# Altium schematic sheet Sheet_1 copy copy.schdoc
size 589 x 414 mm; Device: A_A2; Symbol: A_A2; Name: A_A2; Designator: A; @Project Name: Sheet_1; REV: 1.0; Date: 2023-12-10; Sheet: 1/1; Draw By: sheep_finder; Company: Your Company; Manufacturer Part: ?; Convert to PCB: yes; Add into BOM: yes; Origin Footprint: NONE; Unique ID: frame_lib_1
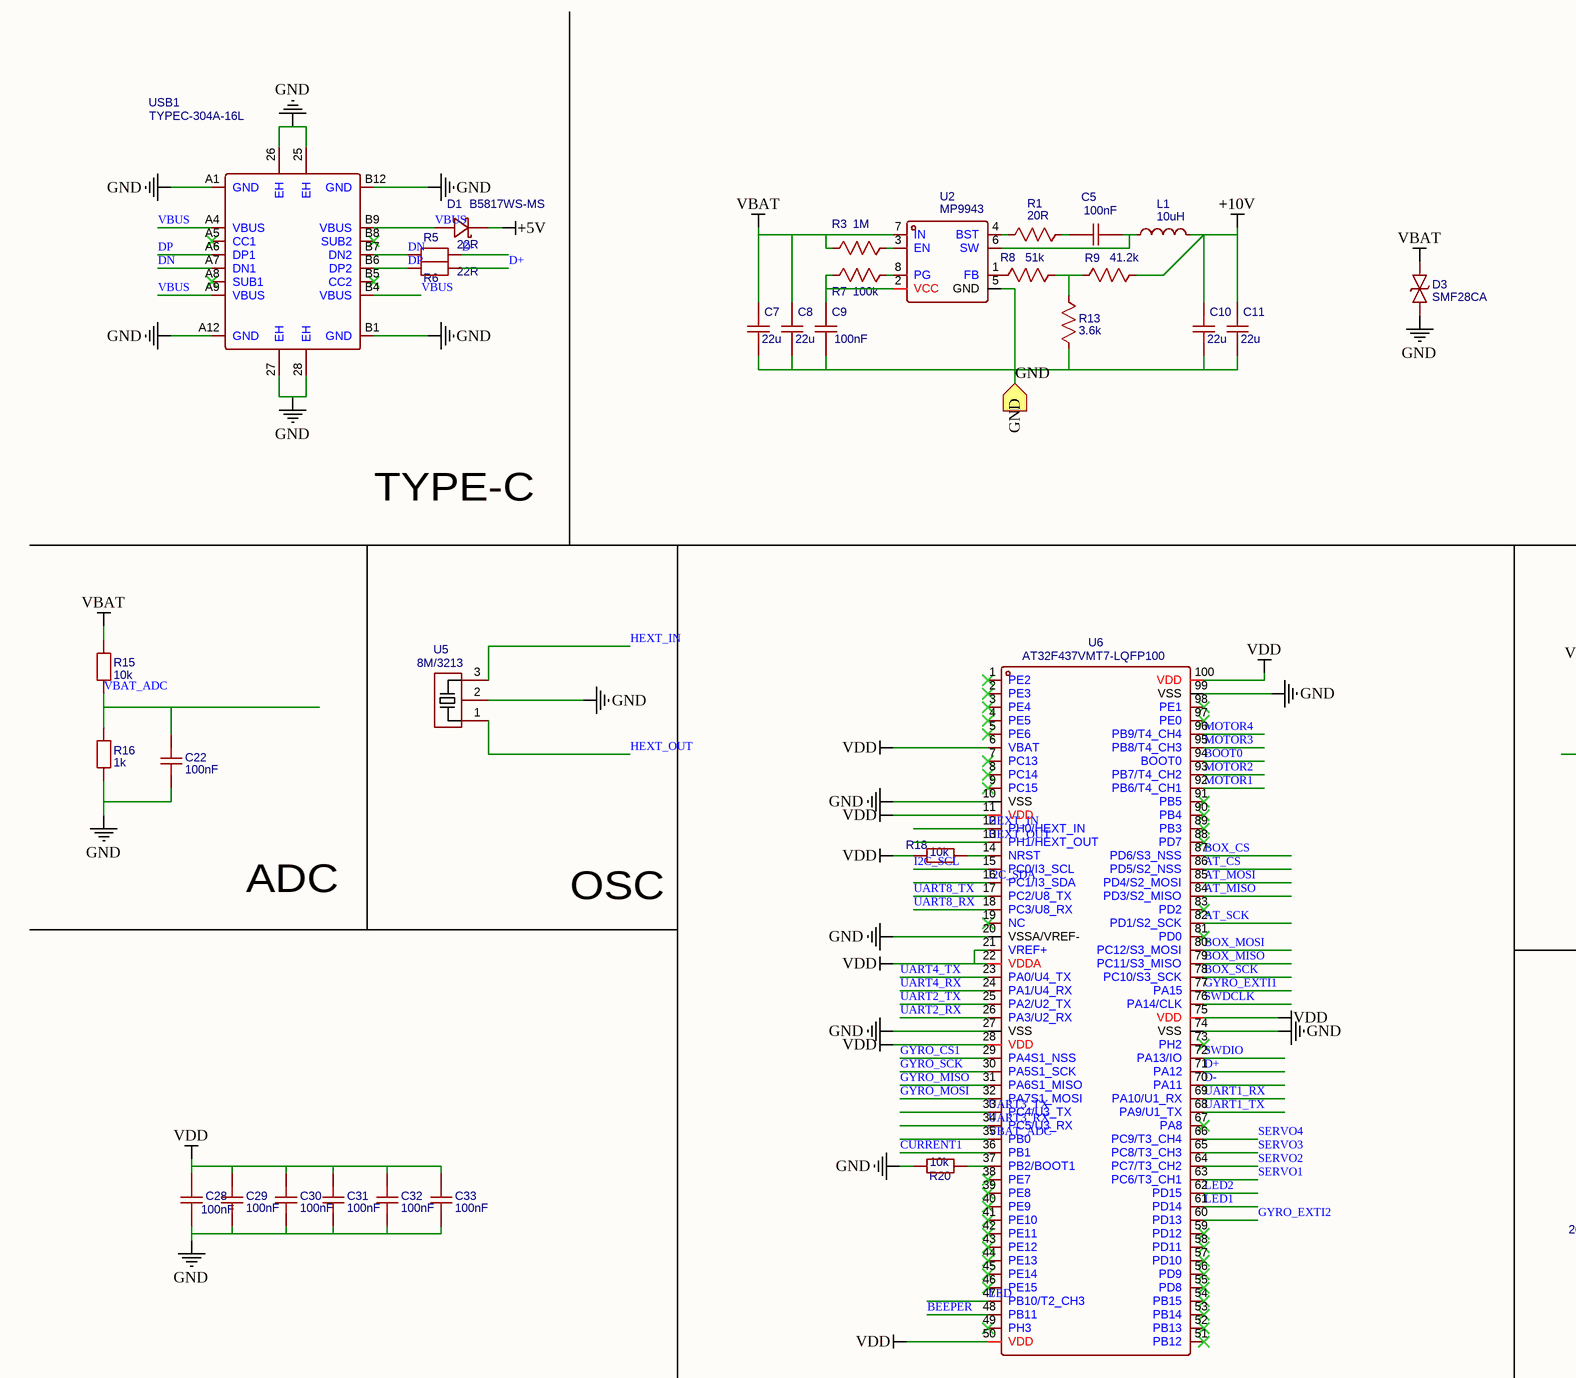
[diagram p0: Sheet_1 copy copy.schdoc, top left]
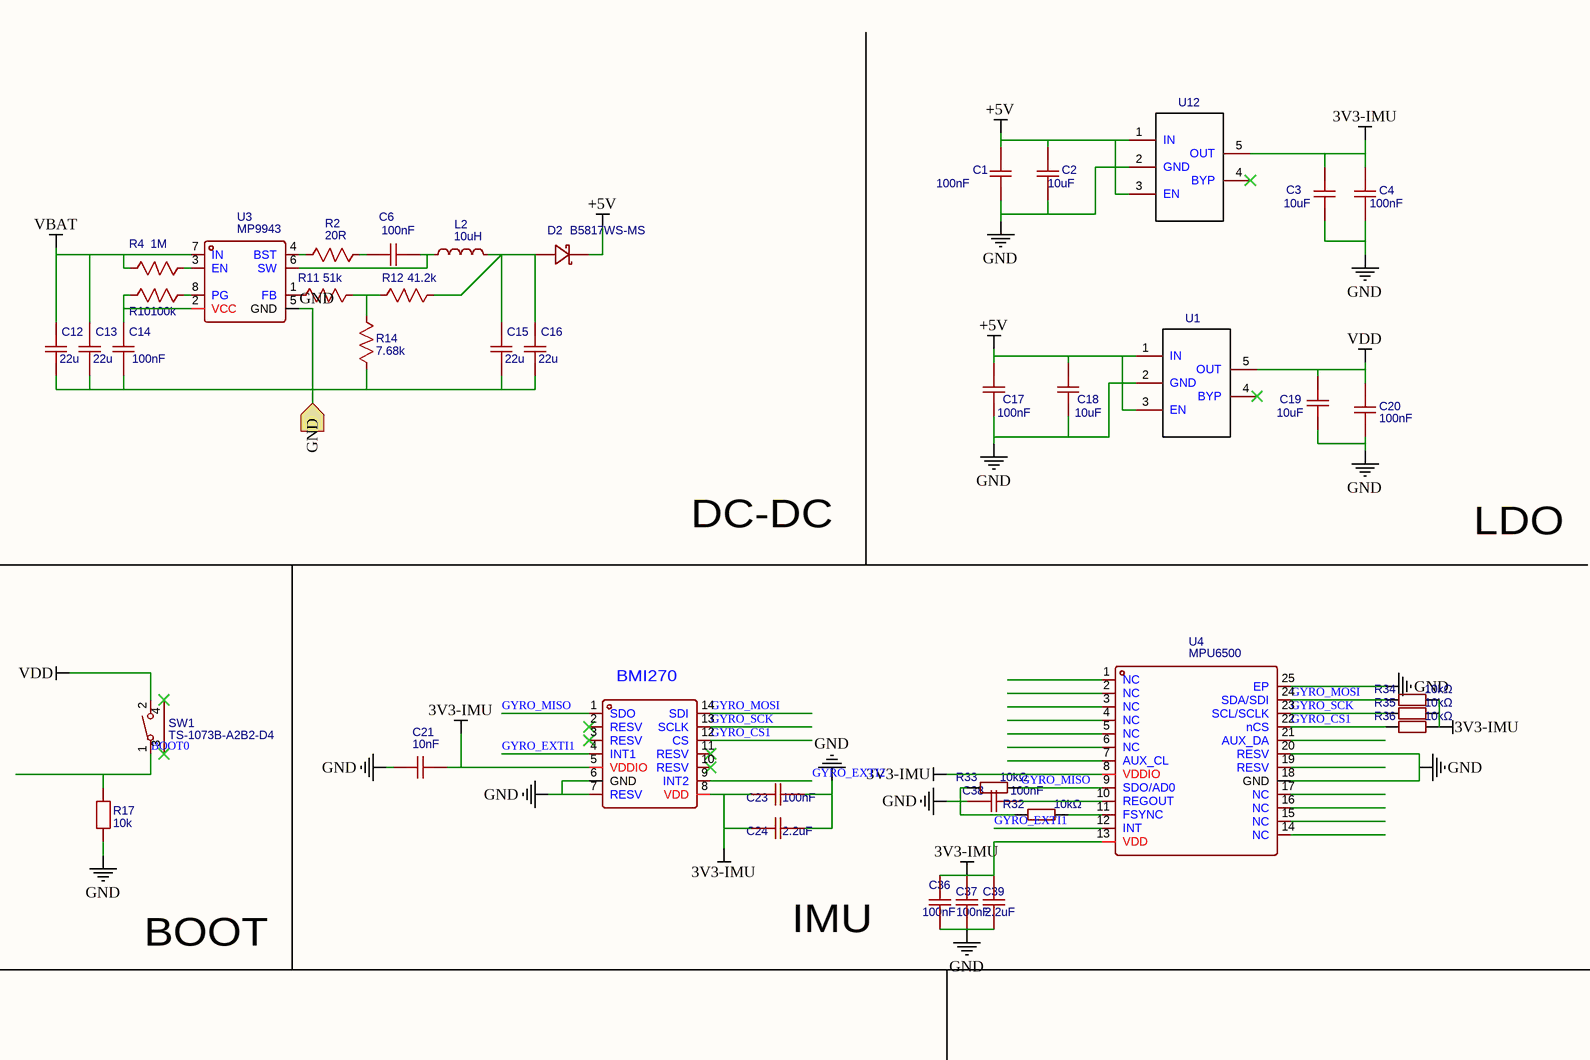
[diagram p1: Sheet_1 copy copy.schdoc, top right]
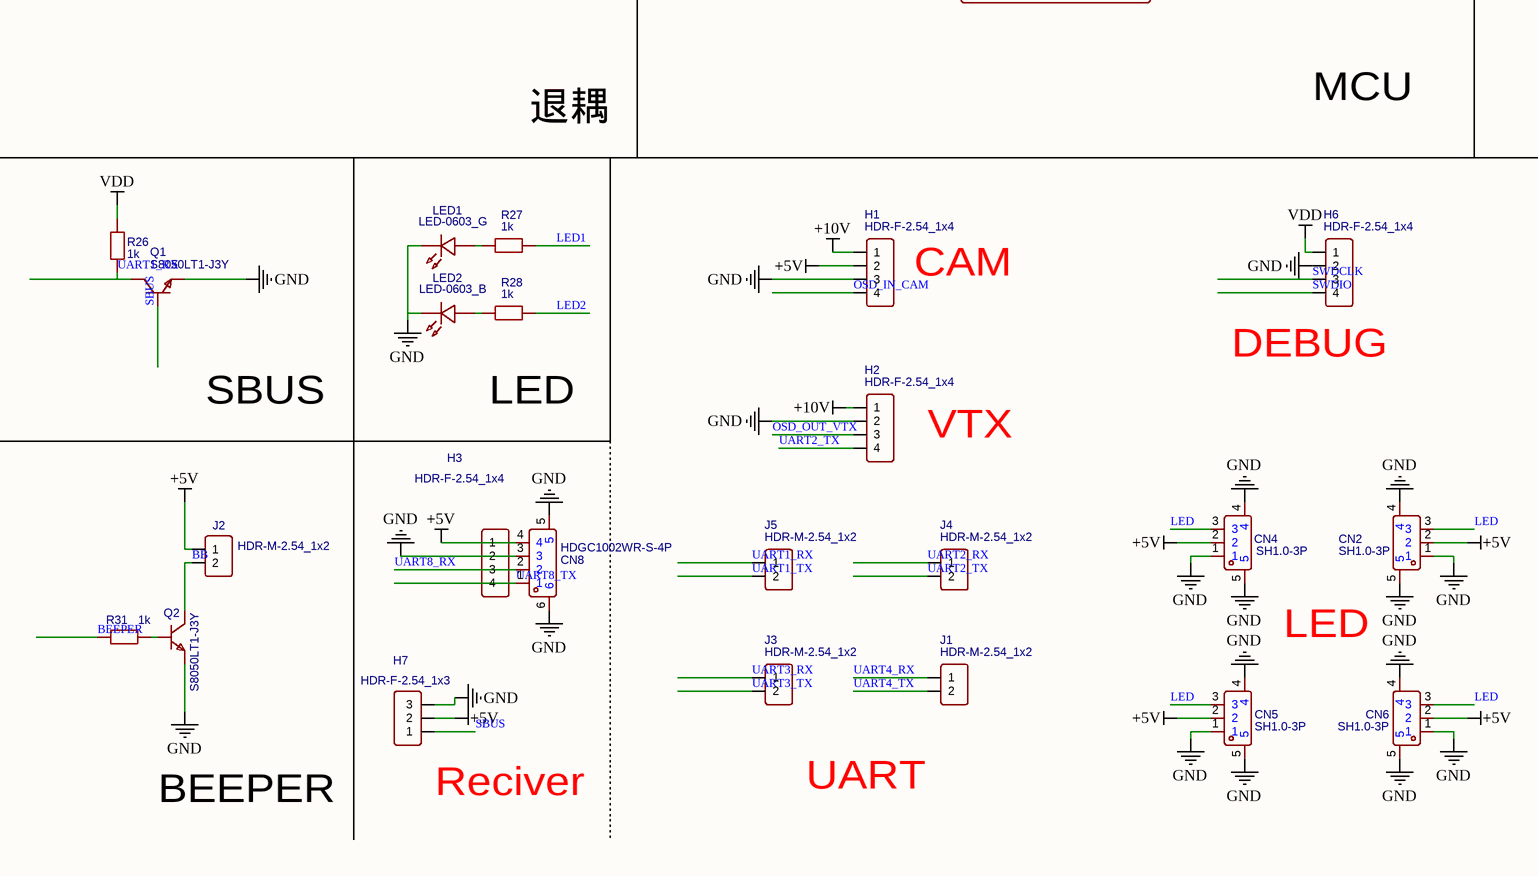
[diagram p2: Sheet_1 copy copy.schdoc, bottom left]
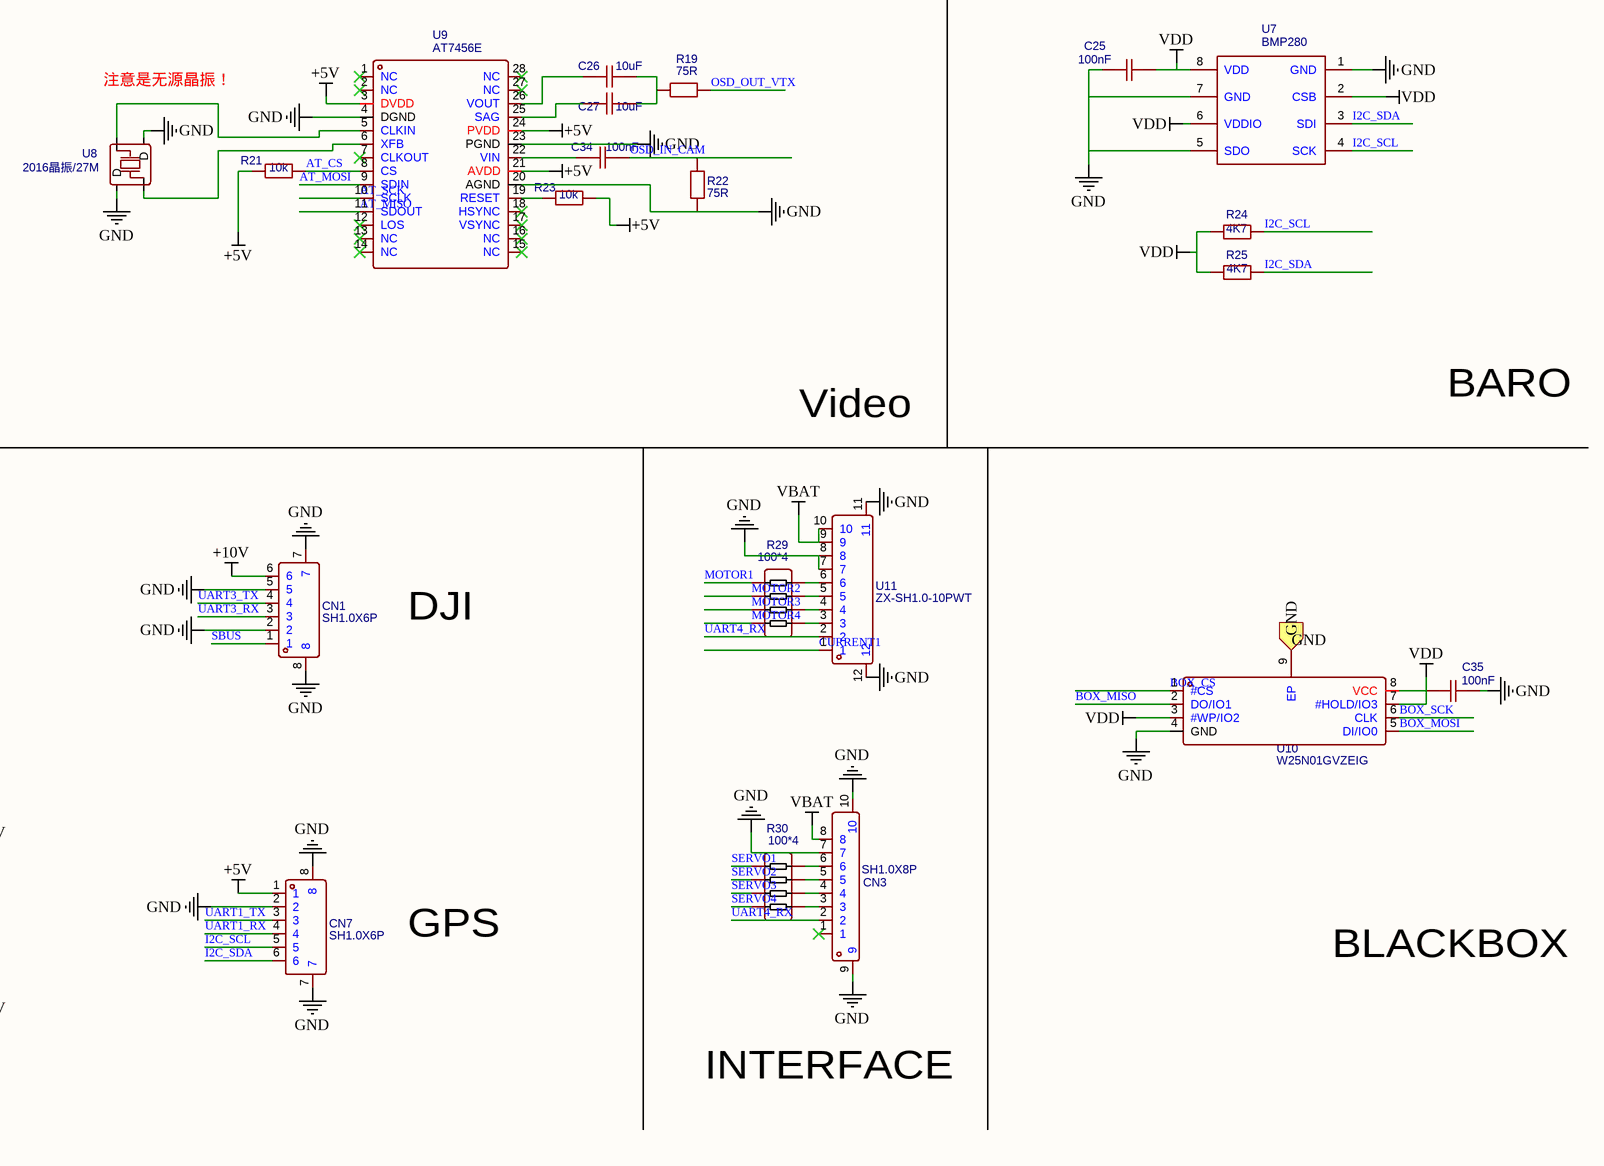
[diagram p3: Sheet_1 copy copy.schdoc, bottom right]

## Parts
C1  100nF  [C0603]
C2  10uF  [C0603]
C3  10uF  [C0603]
C4  100nF  [C0603]
C5  100nF  [C0603]
C6  100nF  [C0603]
C7  22u  [C0805]
C8  22u  [C0805]
C9  100nF  [C0603]
C10  22u  [C0805]
C11  22u  [C0805]
C12  22u  [C0805]
C13  22u  [C0805]
C14  100nF  [C0603]
C15  22u  [C0805]
C16  22u  [C0805]
C17  100nF  [C0603]
C18  10uF  [C0603]
C19  10uF  [C0603]
C20  100nF  [C0603]
C21  10nF  [C0603]
C22  100nF  [C0603]
C23  100nF  [C0603]
C24  2.2uF  [C0603]
C25  100nF  [C0603]
C26  10uF  [C0603]
C27  10uF  [C0603]
C28  100nF  [C0603]
C29  100nF  [C0603]
C30  100nF  [C0603]
C31  100nF  [C0603]
C32  100nF  [C0603]
C33  100nF  [C0603]
C34  100nF  [C0603]
C35  100nF  [C0603]
C36  100nF  [C0603]
C37  100nF  [C0603]
C38  100nF  [C0603]
C39  2.2uF  [C0603]
CN1  SH1.0X6P  [CONN-SMD_6P-P1.00_MEGASTAR_ZX-SH1.0-6PWT]
CN2  SH1.0-3P  [CONN-SMD_3P-P1.00_HDGC_HDGC1002WR-S-3P]
CN3  SH1.0X8P  [CONN-SMD_8P-P1.00_WAFER-SH1.0-8PWB]
CN4  SH1.0-3P  [CONN-SMD_3P-P1.00_HDGC_HDGC1002WR-S-3P]
CN5  SH1.0-3P  [CONN-SMD_3P-P1.00_HDGC_HDGC1002WR-S-3P]
CN6  SH1.0-3P  [CONN-SMD_3P-P1.00_HDGC_HDGC1002WR-S-3P]
CN7  SH1.0X6P  [CONN-SMD_6P-P1.00_MEGASTAR_ZX-SH1.0-6PWT]
CN8  HDGC1002WR-S-4P  [CONN-SMD_4P-P1.00_HDGC_HDGC1002WR-S-4P]
D1  B5817WS-MS  [SOD-323_L1.7-W1.3-LS2.7-FD]
D2  B5817WS-MS  [SOD-323_L1.7-W1.3-LS2.7-FD]
D3  SMF28CA  [SOD-123_L2.7-W1.8-LS3.7-BI]
H1  HDR-F-2.54_1x4
H2  HDR-F-2.54_1x4
H3  HDR-F-2.54_1x4
H6  HDR-F-2.54_1x4
H7  HDR-F-2.54_1x3
J1  HDR-M-2.54_1x2
J2  HDR-M-2.54_1x2
J3  HDR-M-2.54_1x2
J4  HDR-M-2.54_1x2
J5  HDR-M-2.54_1x2
L1  10uH  [IND-SMD_L4.4-W4.0_PHC0420]
L2  10uH  [IND-SMD_L4.4-W4.0_PHC0420]
LED1  LED-0603_G  [LED0603_GREEN]
LED2  LED-0603_B  [LED0603_BLUE]
Q1  S8050LT1-J3Y  [SOT-23_L2.9-W1.3-P1.90-LS2.4-BR]
Q2  S8050LT1-J3Y  [SOT-23_L2.9-W1.3-P1.90-LS2.4-BR]
R1  20R  [R0603]
R2  20R  [R0603]
R3  1M  [R0603]
R4  1M  [R0603]
R5  22R  [R0603]
R6  22R  [R0603]
R7  100k  [R0603]
R8  51k  [R0603]
R9  41.2k  [R0603]
R10  100k  [R0603]
R11  51k  [R0603]
R12  41.2k  [R0603]
R13  3.6k  [R0603]
R14  7.68k  [R0603]
R15  10k  [R0603]
R16  1k  [R0603]
R17  10k  [R0603]
R18  10k  [R0603]
R19  75R  [R0603]
R20  10k  [R0603]
R21  10k  [R0603]
R22  75R  [R0603]
R23  10k  [R0603]
R24  4K7  [R0603]
R25  4K7  [R0603]
R26  1k  [R0603]
R27  1k  [R0603]
R28  1k  [R0603]
R29  100*4  [RES-ARRAY-SMD_0402-8P-L2.0-W1.0-BL]
R30  100*4  [RES-ARRAY-SMD_0402-8P-L2.0-W1.0-BL]
R31  1k  [R0603]
R32  10kΩ  [R0402]
R33  10kΩ  [R0402]
R34  10kΩ  [R0402]
R35  10kΩ  [R0402]
R36  10kΩ  [R0402]
SDO1  BMI270  [LGA-14_L3.0-W2.5-P0.50-TL]  (value not drawn)
SW1  TS-1073B-A2B2-D4  [KEY-SMD_TS-1073B-A2B2-D4]
U1  SPX3819M5-L-3-3/TR  [SOT-23-5_L3.0-W1.7-P0.95-LS2.8-BL]  (value not drawn)
U2  MP9943  [QFN-8-3X3]
U3  MP9943  [QFN-8-3X3]
U4  MPU6500  [QFN-24_L3.0-W3.0-P0.40-BL-EP]
U5  8M/3213  [X3213]
U6  AT32F437VMT7-LQFP100  [LQFP-100_L14.0-W14.0-P0.50-LS16.0-TL]
U7  BMP280  [SENSOR-TH_BMP280-BL]
U8  2016晶振/27M  [2016晶振]
U9  AT7456E  [TSSOP-28_L9.7-W4.4-P0.65-LS6.4-BL-EP5.5]
U10  W25N01GVZEIG  [WSON-8_L8.0-W6.10-P1.27-EP]
U11  ZX-SH1.0-10PWT  [CONN-SMD_10P-P1.00_ZX-SH1.0-10PWT]
U12  SPX3819M5-L-3-3/TR  [SOT-23-5_L3.0-W1.7-P0.95-LS2.8-BL]  (value not drawn)
USB1  TYPEC-304A-16L  [USB-C-SMD_XUNPU_TYPEC-304A-ACP16L]

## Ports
GND (in)

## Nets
3V3-IMU: C3.2 C4.2 C21.2 C23.2 C24.2 C36.1 C37.1 C39.1 R34.2 R35.2 R36.2 SDO1.5(VDDIO) SDO1.8(VDD) U4.8(VDDIO) U4.13(VDD) U12.5(OUT)
+5V: C1.2 C2.2 C17.2 C18.2 CN2.2 CN4.2 CN5.2 CN6.2 CN7.1 CN8.4 D1.2(K) D2.2(K) H1.2 H3.1 H7.2 J2.1 R21.1 R23.2 U1.1(IN) U1.3(EN) U9.3(DVDD) U9.21(AVDD) U9.24(PVDD) U12.1(IN) U12.3(EN)
+10V: C10.2 C11.2 CN1.6 H1.1 H2.1 L1.2 R9.2
GND: C1.1 C2.1 C3.1 C4.1 C7.1 C8.1 C9.1 C10.1 C11.1 C12.1 C13.1 C14.1 C15.1 C16.1 C17.1 C18.1 C19.1 C20.1 C21.1 C22.1 C23.1 C24.1 C25.1 C28.1 C29.1 C30.1 C31.1 C32.1 C33.1 C35.2 C36.2 C37.2 C38.1 C39.2 CN1.2 CN1.5 CN1.7 CN1.8 CN2.1 CN2.4 CN2.5 CN3.7 CN3.9 CN3.10 CN4.1 CN4.4 CN4.5 CN5.1 CN5.4 CN5.5 CN6.1 CN6.4 CN6.5 CN7.2 CN7.7 CN7.8 CN8.3 CN8.5 CN8.6 D3.2 H1.3 H2.2 H3.2 H6.2 H7.3 LED1.2 LED2.2 Q1.2 Q2.2 R13.1 R14.1 R16.1 R17.2 R20.1 R22.1 R32.1 R33.1 SDO1.6(GND) SDO1.7(RESV) U1.2(GND) U2.5(GND) U3.5(GND) U4.18(GND) U4.20(RESV) U4.25(EP) U5.2 U6.10(VSS) U6.20(VSSA/VREF-) U6.27(VSS) U6.74(VSS) U6.99(VSS) U7.1(GND) U7.5(SDO) U7.7(GND) U8.2(D) U8.4(D) U9.4(DGND) U9.20(AGND) U9.23(PGND) U10.4(GND) U10.9(EP) U11.7 U11.8 U11.11 U11.12 U12.2(GND) USB1.25(EH) USB1.26(EH) USB1.27(EH) USB1.28(EH) USB1.A1(GND) USB1.A12(GND) USB1.B1(GND) USB1.B12(GND) ; port GND
VBAT: C7.2 C8.2 C12.2 C13.2 CN3.8 D3.1 R3.2 R4.2 R15.2 U2.7(IN) U3.7(IN) U11.9 U11.10
VDD: C19.2 C20.2 C25.2 C28.2 C29.2 C30.2 C31.2 C32.2 C33.2 C35.1 H6.1 R18.2 R24.2 R25.2 R26.2 SW1.2 U1.5(OUT) U6.6(VBAT) U6.11(VDD) U6.21(VREF+) U6.22(VDDA) U6.28(VDD) U6.50(VDD) U6.75(VDD) U6.100(VDD) U7.2(CSB) U7.6(VDDIO) U7.8(VDD) U10.3(#WP/IO2) U10.7(#HOLD/IO3) U10.8(VCC)
AT_CS: R21.2 U6.86(PD5/S2_NSS) U9.8(CS)
AT_MISO: U6.84(PD3/S2_MISO) U9.11(SDOUT)
AT_MOSI: U6.85(PD4/S2_MOSI) U9.9(SDIN)
AT_SCK: U6.82(PD1/S2_SCK) U9.10(SCLK)
BB: J2.2 Q2.3
BEEPER: R31.1 U6.48(PB11)
BOOT0: R17.1 SW1.1 U6.94(BOOT0)
BOX_CS: U6.87(PD6/S3_NSS) U10.1(#CS)
BOX_MISO: U6.79(PC11/S3_MISO) U10.2(DO/IO1)
BOX_MOSI: U6.80(PC12/S3_MOSI) U10.5(DI/IO0)
BOX_SCK: U6.78(PC10/S3_SCK) U10.6(CLK)
CURRENT1: U6.36(PB1) U11.1
D+: R6.2 U6.71(PA12)
D-: R5.2 U6.70(PA11)
DN: R5.1 USB1.A7(DN1) USB1.B7(DN2)
DP: R6.1 USB1.A6(DP1) USB1.B6(DP2)
GYRO_CS1: R36.1 SDO1.12(CS) U4.22(nCS) U6.29(PA4S1_NSS)
GYRO_EXTI1: SDO1.4(INT1) U4.12(INT) U6.77(PA15)
GYRO_EXTI2: SDO1.9(INT2) U6.60(PD13)
GYRO_MISO: R33.2 SDO1.1(SDO) U4.9(SDO/AD0) U6.31(PA6S1_MISO)
GYRO_MOSI: R34.1 SDO1.14(SDI) U4.24(SDA/SDI) U6.32(PA7S1_MOSI)
GYRO_SCK: R35.1 SDO1.13(SCLK) U4.23(SCL/SCLK) U6.30(PA5S1_SCK)
HEXT_IN: U5.3 U6.12(PH0/HEXT_IN)
HEXT_OUT: U5.1 U6.13(PH1/HEXT_OUT)
I2C_SCL: CN7.5 R24.1 U6.15(PC0/I3_SCL) U7.4(SCK)
I2C_SDA: CN7.6 R25.1 U6.16(PC1/I3_SDA) U7.3(SDI)
LED: CN2.3 CN4.3 CN5.3 CN6.3 U6.47(PB10/T2_CH3)
LED1: R27.2 U6.61(PD14)
LED2: R28.2 U6.62(PD15)
MOTOR1: R29.4 U6.92(PB6/T4_CH1)
MOTOR2: R29.3 U6.93(PB7/T4_CH2)
MOTOR3: R29.2 U6.95(PB8/T4_CH3)
MOTOR4: R29.1 U6.96(PB9/T4_CH4)
OSD_IN_CAM: C34.2 H1.4 R22.2
OSD_OUT_VTX: H2.3 R19.2
SBUS: CN1.1 H7.1 Q1.1
SERVO1: R30.4 U6.63(PC6/T3_CH1)
SERVO2: R30.3 U6.64(PC7/T3_CH2)
SERVO3: R30.2 U6.65(PC8/T3_CH3)
SERVO4: R30.1 U6.66(PC9/T3_CH4)
SWDCLK: H6.3 U6.76(PA14/CLK)
SWDIO: H6.4 U6.72(PA13/IO)
UART1_RX: CN7.4 J5.1 Q1.3 R26.1 U6.69(PA10/U1_RX)
UART1_TX: CN7.3 J5.2 U6.68(PA9/U1_TX)
UART2_RX: J4.1 U6.26(PA3/U2_RX)
UART2_TX: H2.4 J4.2 U6.25(PA2/U2_TX)
UART3_RX: CN1.3 J3.1 U6.34(PC5/U3_RX)
UART3_TX: CN1.4 J3.2 U6.33(PC4/U3_TX)
UART4_RX: CN3.2 J1.1 U6.24(PA1/U4_RX) U11.2
UART4_TX: J1.2 U6.23(PA0/U4_TX)
UART8_RX: CN8.2 H3.3 U6.18(PC3/U8_RX)
UART8_TX: CN8.1 H3.4 U6.17(PC2/U8_TX)
VBAT_ADC: C22.2 R15.1 R16.2 U6.35(PB0)
VBUS: D1.1(A) USB1.A4(VBUS) USB1.A9(VBUS) USB1.B4(VBUS) USB1.B9(VBUS)
NetC5_1: C5.1 R1.2
NetC5_2: C5.2 L1.1 U2.6(SW)
NetC6_1: C6.1 R2.2
NetC6_2: C6.2 L2.1 U3.6(SW)
NetC9_2: C9.2 R7.1 U2.2(VCC)
NetC14_2: C14.2 R10.1 U3.2(VCC)
NetC15_2: C15.2 C16.2 D2.1(A) L2.2 R12.2
NetC26_1: C26.1 C27.1 R19.1
NetC26_2: C26.2 U9.26(VOUT)
NetC27_2: C27.2 U9.25(SAG)
NetC34_1: C34.1 U9.22(VIN)
NetC38_2: C38.2 U4.10(REGOUT)
NetCN3_3: CN3.3 R30.8
NetCN3_4: CN3.4 R30.7
NetCN3_5: CN3.5 R30.6
NetCN3_6: CN3.6 R30.5
NetLED1_1: LED1.1 R27.1
NetLED2_1: LED2.1 R28.1
NetQ2_1: Q2.1 R31.2
NetR1_1: R1.1 U2.4(BST)
NetR2_1: R2.1 U3.4(BST)
NetR3_1: R3.1 U2.3(EN)
NetR4_1: R4.1 U3.3(EN)
NetR7_2: R7.2 U2.8(PG)
NetR8_1: R8.1 U2.1(FB)
NetR8_2: R8.2 R9.1 R13.2
NetR10_2: R10.2 U3.8(PG)
NetR11_1: R11.1 U3.1(FB)
NetR11_2: R11.2 R12.1 R14.2
NetR18_1: R18.1 U6.14(NRST)
NetR20_2: R20.2 U6.37(PB2/BOOT1)
NetR23_1: R23.1 U9.19(RESET)
NetR29_5: R29.5 U11.6
NetR29_6: R29.6 U11.5
NetR29_7: R29.7 U11.4
NetR29_8: R29.8 U11.3
NetR32_2: R32.2 U4.11(FSYNC)
NetU8_1: U8.1(OSC1) U9.5(CLKIN)
NetU8_3: U8.3(OSC2) U9.6(XFB)

Not connected (* = marked no-connect by the designer): CN3 1*; SDO1 2(RESV)* 3(RESV)* 10(RESV)* 11(RESV)*; SW1 3* 4*; U1 4(BYP)*; U4 1(NC) 2(NC) 3(NC) 4(NC) 5(NC) 6(NC) 7(AUX_CL) 14(NC) 15(NC) 16(NC) 17(NC) 19(RESV) 21(AUX_DA); U6 1(PE2)* 2(PE3)* 3(PE4)* 4(PE5)* 5(PE6)* 7(PC13)* 8(PC14)* 9(PC15)* 19(NC)* 38(PE7)* 39(PE8)* 40(PE9)* 41(PE10)* 42(PE11)* 43(PE12)* 44(PE13)* 45(PE14)* 46(PE15)* 49(PH3)* 51(PB12)* 52(PB13)* 53(PB14)* 54(PB15)* 55(PD8)* 56(PD9)* 57(PD10)* 58(PD11)* 59(PD12)* 67(PA8)* 73(PH2)* 81(PD0)* 83(PD2)* 88(PD7)* 89(PB3)* 90(PB4)* 91(PB5)* 97(PE0)* 98(PE1)*; U9 1(NC)* 2(NC)* 7(CLKOUT)* 12(LOS)* 13(NC)* 14(NC)* 15(NC)* 16(NC)* 17(VSYNC)* 18(HSYNC)* 27(NC)* 28(NC)*; U12 4(BYP)*; USB1 A5(CC1)* A8(SUB1)* B5(CC2)* B8(SUB2)*

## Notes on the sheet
- TYPE-C
- DC-DC
- LDO
- (near SDO1) BMI270
- ADC
- OSC
- BOOT
- IMU
- 注意是无源晶振！
- 退耦
- MCU
- Video
- BARO
- (near H1) CAM
- DJI
- SBUS
- LED
- (near H6) DEBUG
- VTX
- GPS
- BLACKBOX
- BEEPER
- (near H7) Reciver
- UART
- INTERFACE

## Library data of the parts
C1 = 100nF: Convert to PCB: yes; UniqueId: ggeca7b0ddeeb75bee7; OriginModelName: C0603_L1.6-W0.8-H0.8; ModelTransform: 62.992,31.496,0,0,0,0,0,0,0
C2 = 10uF: Convert to PCB: yes; UniqueId: gge5965a6e0a8e1c0df; OriginModelName: C0603_L1.6-W0.8-H0.8; ModelTransform: 62.992,31.496,0,0,0,0,0,0,0
C3 = 10uF: Convert to PCB: yes; UniqueId: ggee7971eff1ce66244; OriginModelName: C0603_L1.6-W0.8-H0.8; ModelTransform: 62.992,31.496,0,0,0,0,0,0,0
C4 = 100nF: Convert to PCB: yes; UniqueId: gge7ba523bb7e9eb41d; OriginModelName: C0603_L1.6-W0.8-H0.8; ModelTransform: 62.992,31.496,0,0,0,0,0,0,0
C5 = 100nF: Convert to PCB: yes; UniqueId: gge52ce95ff5addf7c7; OriginModelName: C0603_L1.6-W0.8-H0.8; ModelTransform: 62.992,31.496,0,0,0,0,0,0,0
C6 = 100nF: Convert to PCB: yes; UniqueId: ggecda314712177e332; OriginModelName: C0603_L1.6-W0.8-H0.8; ModelTransform: 62.992,31.496,0,0,0,0,0,0,0
C7 = 22u: Convert to PCB: yes; UniqueId: gge353fd94c7c744818; OriginModelName: C0805_L2.0-W1.3-H1.3; ModelTransform: 78.74,51.181,0,0,0,0,0,0,0
C8 = 22u: Convert to PCB: yes; UniqueId: gge3f3579b26317b48f; OriginModelName: C0805_L2.0-W1.3-H1.3; ModelTransform: 78.74,51.181,0,0,0,0,0,0,0
C9 = 100nF: Convert to PCB: yes; UniqueId: gge6703928f547b0b14; OriginModelName: C0603_L1.6-W0.8-H0.8; ModelTransform: 62.992,31.496,0,0,0,0,0,0,0
C10 = 22u: Convert to PCB: yes; UniqueId: ggea3c3f9500a281c6b; OriginModelName: C0805_L2.0-W1.3-H1.3; ModelTransform: 78.74,51.181,0,0,0,0,0,0,0
C11 = 22u: Convert to PCB: yes; UniqueId: gge2484e21a77e28d03; OriginModelName: C0805_L2.0-W1.3-H1.3; ModelTransform: 78.74,51.181,0,0,0,0,0,0,0
C12 = 22u: Convert to PCB: yes; UniqueId: gge7b8deaa52abeee98; OriginModelName: C0805_L2.0-W1.3-H1.3; ModelTransform: 78.74,51.181,0,0,0,0,0,0,0
C13 = 22u: Convert to PCB: yes; UniqueId: gge0c0d9a2245dd9bee; OriginModelName: C0805_L2.0-W1.3-H1.3; ModelTransform: 78.74,51.181,0,0,0,0,0,0,0
C14 = 100nF: Convert to PCB: yes; UniqueId: ggeb64b90ee87dd39cb; OriginModelName: C0603_L1.6-W0.8-H0.8; ModelTransform: 62.992,31.496,0,0,0,0,0,0,0
C15 = 22u: Convert to PCB: yes; UniqueId: gge32340f00fe0e8bd0; OriginModelName: C0805_L2.0-W1.3-H1.3; ModelTransform: 78.74,51.181,0,0,0,0,0,0,0
C16 = 22u: Convert to PCB: yes; UniqueId: ggee6eb9f67a65547cc; OriginModelName: C0805_L2.0-W1.3-H1.3; ModelTransform: 78.74,51.181,0,0,0,0,0,0,0
C17 = 100nF: Convert to PCB: yes; UniqueId: ggea85fba6b31ef2400; OriginModelName: C0603_L1.6-W0.8-H0.8; ModelTransform: 62.992,31.496,0,0,0,0,0,0,0
C18 = 10uF: Convert to PCB: yes; UniqueId: gge4c0cbcdc33413a46; OriginModelName: C0603_L1.6-W0.8-H0.8; ModelTransform: 62.992,31.496,0,0,0,0,0,0,0
C19 = 10uF: Convert to PCB: yes; UniqueId: gge6e9699387ec808ae; OriginModelName: C0603_L1.6-W0.8-H0.8; ModelTransform: 62.992,31.496,0,0,0,0,0,0,0
C20 = 100nF: Convert to PCB: yes; UniqueId: ggedb2a942aedfaf0e5; OriginModelName: C0603_L1.6-W0.8-H0.8; ModelTransform: 62.992,31.496,0,0,0,0,0,0,0
C21 = 10nF: Convert to PCB: yes; UniqueId: ggecba86c4f4db73d07; OriginModelName: C0603_L1.6-W0.8-H0.8; ModelTransform: 62.992,31.496,0,0,0,0,0,0,0
C22 = 100nF: Convert to PCB: yes; UniqueId: gged673bfa93339740f; OriginModelName: C0603_L1.6-W0.8-H0.8; ModelTransform: 62.992,31.496,0,0,0,0,0,0,0
C23 = 100nF: Convert to PCB: yes; UniqueId: gge03e79812ca9f1594; OriginModelName: C0603_L1.6-W0.8-H0.8; ModelTransform: 62.992,31.496,0,0,0,0,0,0,0
C24 = 2.2uF: Convert to PCB: yes; UniqueId: gge194ad5a5974422c7; OriginModelName: C0603_L1.6-W0.8-H0.8; ModelTransform: 62.992,31.496,0,0,0,0,0,0,0
C25 = 100nF: Convert to PCB: yes; UniqueId: ggec38fa6919078953f; OriginModelName: C0603_L1.6-W0.8-H0.8; ModelTransform: 62.992,31.496,0,0,0,0,0,0,0
C26 = 10uF: Convert to PCB: yes; UniqueId: ggeeb9301ced7e232ca; OriginModelName: C0603_L1.6-W0.8-H0.8; ModelTransform: 62.992,31.496,0,0,0,0,0,0,0
C27 = 10uF: Convert to PCB: yes; UniqueId: gge9a113f5a677df9d8; OriginModelName: C0603_L1.6-W0.8-H0.8; ModelTransform: 62.992,31.496,0,0,0,0,0,0,0
C28 = 100nF: Convert to PCB: yes; UniqueId: ggef40206292685441e; OriginModelName: C0603_L1.6-W0.8-H0.8; ModelTransform: 62.992,31.496,0,0,0,0,0,0,0
C29 = 100nF: Convert to PCB: yes; UniqueId: gge2ebcfc57574d399a; OriginModelName: C0603_L1.6-W0.8-H0.8; ModelTransform: 62.992,31.496,0,0,0,0,0,0,0
C30 = 100nF: Convert to PCB: yes; UniqueId: gged33014bcecda883b; OriginModelName: C0603_L1.6-W0.8-H0.8; ModelTransform: 62.992,31.496,0,0,0,0,0,0,0
C31 = 100nF: Convert to PCB: yes; UniqueId: ggee2bd2f168eb7a19f; OriginModelName: C0603_L1.6-W0.8-H0.8; ModelTransform: 62.992,31.496,0,0,0,0,0,0,0
C32 = 100nF: Convert to PCB: yes; UniqueId: ggedee51cfaf3930afd; OriginModelName: C0603_L1.6-W0.8-H0.8; ModelTransform: 62.992,31.496,0,0,0,0,0,0,0
C33 = 100nF: Convert to PCB: yes; UniqueId: gge26811f5395af21ce; OriginModelName: C0603_L1.6-W0.8-H0.8; ModelTransform: 62.992,31.496,0,0,0,0,0,0,0
C34 = 100nF: Convert to PCB: yes; UniqueId: gge8daa5e5140b19545; OriginModelName: C0603_L1.6-W0.8-H0.8; ModelTransform: 62.992,31.496,0,0,0,0,0,0,0
C35 = 100nF: Convert to PCB: yes; UniqueId: gge108316898df37a9f; OriginModelName: C0603_L1.6-W0.8-H0.8; ModelTransform: 62.992,31.496,0,0,0,0,0,0,0
C36 = 100nF: Convert to PCB: yes; UniqueId: gge1844c11426338be2; OriginModelName: C0603_L1.6-W0.8-H0.8; ModelTransform: 62.992,31.496,0,0,0,0,0,0,0
C37 = 100nF: Convert to PCB: yes; UniqueId: ggefc1b89ea0528c883; OriginModelName: C0603_L1.6-W0.8-H0.8; ModelTransform: 62.992,31.496,0,0,0,0,0,0,0
C38 = 100nF: Convert to PCB: yes; UniqueId: gge2b0adef4c2000f72; OriginModelName: C0603_L1.6-W0.8-H0.8; ModelTransform: 62.992,31.496,0,0,0,0,0,0,0
C39 = 2.2uF: Convert to PCB: yes; UniqueId: gge6b0287d4c016d85a; OriginModelName: C0603_L1.6-W0.8-H0.8; ModelTransform: 62.992,31.496,0,0,0,0,0,0,0
CN1 = ZX-SH1.0-6PWT: Manufacturer: Megastar(兆星); Convert to PCB: yes; UniqueId: ggecd9d3fcf4734ba22; ModelTransform: 329.1332,198.8185,0,0,0,0,0.002,-7.876,0
CN2 = HDGC1002WR-S-3P: Manufacturer: HDGC(华德共创); Convert to PCB: yes; UniqueId: gge2ce44b7eaad9832b; ModelTransform: 210.63,196.85,0,0,0,0,0,-9.565,0
CN3 = WAFER_SMT_1.0X8: Manufacturer: null; Convert to PCB: yes; UniqueId: ggebe725300a9fc9f2b; ModelTransform: 407.873,198.8185,0,0,0,0,-0.001,-16.732,0
CN4 = HDGC1002WR-S-3P: Manufacturer: HDGC(华德共创); Convert to PCB: yes; UniqueId: ggec0020a35e89ad4ff; ModelTransform: 210.63,196.85,0,0,0,0,0,-9.565,0
CN5 = HDGC1002WR-S-3P: Manufacturer: HDGC(华德共创); Convert to PCB: yes; UniqueId: gge5e0003f38aa131f5; ModelTransform: 210.63,196.85,0,0,0,0,0,-9.565,0
CN6 = HDGC1002WR-S-3P: Manufacturer: HDGC(华德共创); Convert to PCB: yes; UniqueId: ggecca6adc977efc5d6; ModelTransform: 210.63,196.85,0,0,0,0,0,-9.565,0
CN7 = ZX-SH1.0-6PWT: Manufacturer: Megastar(兆星); Convert to PCB: yes; UniqueId: gge7f46dd2bd5c42fec; ModelTransform: 329.1332,198.8185,0,0,0,0,0.002,-7.876,0
CN8 = HDGC1002WR-S-4P: Manufacturer: HDGC(华德共创); Convert to PCB: yes; UniqueId: ggee5a51ee7bd50bb1d; ModelTransform: 249.9995,196.85,0,0,0,0,0,-5.906,0
D1 = B5817WS-MS: Manufacturer: MSKSEMI(美森科); Convert to PCB: yes; UniqueId: gge7bf08ecfc7523faa; ModelTransform: 104.3305,51.181,0,0,0,0,0,0,0
D2 = B5817WS-MS: Manufacturer: MSKSEMI(美森科); Convert to PCB: yes; UniqueId: gge33ebbc6fa40b7b0c; ModelTransform: 104.3305,51.181,0,0,0,0,0,0,0
D3 = SMF28CA: Manufacturer: AnBon(安邦); Convert to PCB: yes; UniqueId: gge8336ca0810bb463b; ModelTransform: 145.669,70.866,0,0,0,0,0,0,0
H1 = HDR-F-2.54_1x4: Convert to PCB: no; UniqueId: gge885eefff489981f5
H2 = HDR-F-2.54_1x4: Convert to PCB: no; UniqueId: ggeb2604217fb50aa1f
H3 = HDR-F-2.54_1x4: Convert to PCB: no; UniqueId: ggee6be973db10bda17
H6 = HDR-F-2.54_1x4: Convert to PCB: no; UniqueId: ggeb577fd7058a0a445
H7 = HDR-F-2.54_1x3: Convert to PCB: no; UniqueId: ggeb90c589a3958aeec
J1 = HDR-M-2.54_1x2: Convert to PCB: no; UniqueId: gge963c905d1ba80b10
J2 = HDR-M-2.54_1x2: Convert to PCB: no; UniqueId: gge45273bc977e0dc7f
J3 = HDR-M-2.54_1x2: Convert to PCB: no; UniqueId: gge86939b4fd004270e
J4 = HDR-M-2.54_1x2: Convert to PCB: no; UniqueId: gge368a583462a7af64
J5 = HDR-M-2.54_1x2: Convert to PCB: no; UniqueId: gge12fcbeb4db2ab241
L1 = PHC0420-100M-T: Manufacturer: EMTEK; Convert to PCB: yes; UniqueId: gge99af4ca34bfde78c; OriginModelName: IND-SMD_L4.4-W4.0-H1.2_PHC0420; ModelTransform: 175.1965,159.842,0,0,0,0,0,0,0
L2 = PHC0420-100M-T: Manufacturer: EMTEK; Convert to PCB: yes; UniqueId: gge7b26eb143931701e; OriginModelName: IND-SMD_L4.4-W4.0-H1.2_PHC0420; ModelTransform: 175.1965,159.842,0,0,0,0,0,0,0
LED1 = 19-217/GHC-YR1S2/3T: Manufacturer: EVERLIGHT(台湾亿光); Convert to PCB: yes; UniqueId: ggec33a0d43bf0fd1a5; OriginModelName: LED0603-RD_GREEN; ModelTransform: 63.7794,31.496,0,0,0,0,0,0,0
LED2 = 19-217/BHC-ZL1M2RY/3T: Manufacturer: EVERLIGHT(台湾亿光); Convert to PCB: yes; UniqueId: gge88f0d97242bbc373; ModelTransform: 63.07074,31.57474,0,180,0,0,0,0,0
Q1 = S8050LT1-J3Y: Manufacturer: FH(风华); Convert to PCB: yes; UniqueId: gge1c8eb3e3ebf663b6; OriginModelName: SOT-23-3P_L2.9-W1.3-H1.0-LS2.4-P0.95; ModelTransform: 98.64468,114.173,0,180,0,0,0.001,0.001,0
Q2 = S8050LT1-J3Y: Manufacturer: FH(风华); Convert to PCB: yes; UniqueId: gge7f16b287a280f568; OriginModelName: SOT-23-3P_L2.9-W1.3-H1.0-LS2.4-P0.95; ModelTransform: 98.64468,114.173,0,180,0,0,0.001,0.001,0
R1 = 20R: Convert to PCB: yes; UniqueId: gge2803cdfef027f426; ModelTransform: 31.8897,63.7794,0,90,0,0,0,0,0
R2 = 20R: Convert to PCB: yes; UniqueId: ggeae51583009f5c62d; ModelTransform: 31.8897,63.7794,0,90,0,0,0,0,0
R3 = 1M: Convert to PCB: yes; UniqueId: gge718708ee9e31e9c6; ModelTransform: 31.8897,63.7794,0,90,0,0,0,0,0
R4 = 1M: Convert to PCB: yes; UniqueId: ggee74e946aa43fe3b1; ModelTransform: 31.8897,63.7794,0,90,0,0,0,0,0
R5 = 22R: Convert to PCB: yes; UniqueId: gge1054e90f8c2270dd; ModelTransform: 31.8897,63.7794,0,90,0,0,0,0,0
R6 = 22R: Convert to PCB: yes; UniqueId: gge376c1236b153a772; ModelTransform: 31.8897,63.7794,0,90,0,0,0,0,0
R7 = 100k: Convert to PCB: yes; UniqueId: gge65a4b7670a104600; ModelTransform: 31.8897,63.7794,0,90,0,0,0,0,0
R8 = 51k: Convert to PCB: yes; UniqueId: gge9fd81eef2a8f7ffa; ModelTransform: 31.8897,63.7794,0,90,0,0,0,0,0
R9 = 41.2k: Convert to PCB: yes; UniqueId: gge9f85a8b729309dec; ModelTransform: 31.8897,63.7794,0,90,0,0,0,0,0
R10 = 100k: Convert to PCB: yes; UniqueId: gge19e236c747ebd94a; ModelTransform: 31.8897,63.7794,0,90,0,0,0,0,0
R11 = 51k: Convert to PCB: yes; UniqueId: gge0f1b7351eff14f5c; ModelTransform: 31.8897,63.7794,0,90,0,0,0,0,0
R12 = 41.2k: Convert to PCB: yes; UniqueId: ggeaf2d57fb3ee954de; ModelTransform: 31.8897,63.7794,0,90,0,0,0,0,0
R13 = 3.6k: Convert to PCB: yes; UniqueId: gge2804a892dc8b5d22; ModelTransform: 31.8897,63.7794,0,90,0,0,0,0,0
R14 = 7.68k: Convert to PCB: yes; UniqueId: gge438bc0fbe55c7c82; ModelTransform: 31.8897,63.7794,0,90,0,0,0,0,0
R15 = 10k: Convert to PCB: yes; UniqueId: ggeb37841dcc2a40db6; ModelTransform: 31.8897,63.7794,0,90,0,0,0,0,0
R16 = 1k: Convert to PCB: yes; UniqueId: gge14669116017803cb; ModelTransform: 31.8897,63.7794,0,90,0,0,0,0,0
R17 = 10k: Convert to PCB: yes; UniqueId: ggecda1f708b81c7ca6; ModelTransform: 31.8897,63.7794,0,90,0,0,0,0,0
R18 = 10k: Convert to PCB: yes; UniqueId: gge74c37a84cb754f85; ModelTransform: 31.8897,63.7794,0,90,0,0,0,0,0
R19 = 75R: Convert to PCB: yes; UniqueId: gge99ad03ce5fc1563c; ModelTransform: 31.8897,63.7794,0,90,0,0,0,0,0
R20 = 10k: Convert to PCB: yes; UniqueId: ggecccef22c02713413; ModelTransform: 31.8897,63.7794,0,90,0,0,0,0,0
R21 = 10k: Convert to PCB: yes; UniqueId: ggecb38663ade157f52; ModelTransform: 31.8897,63.7794,0,90,0,0,0,0,0
R22 = 75R: Convert to PCB: yes; UniqueId: gge175528db6f6a6a66; ModelTransform: 31.8897,63.7794,0,90,0,0,0,0,0
R23 = 10k: Convert to PCB: yes; UniqueId: ggee41f9b045fab3390; ModelTransform: 31.8897,63.7794,0,90,0,0,0,0,0
R24 = 4K7: Convert to PCB: yes; UniqueId: gge096ca4e081fb04e8; ModelTransform: 31.8897,63.7794,0,90,0,0,0,0,0
R25 = 4K7: Convert to PCB: yes; UniqueId: gge5e765753ece9e3c8; ModelTransform: 31.8897,63.7794,0,90,0,0,0,0,0
R26 = 1k: Convert to PCB: yes; UniqueId: ggee0760564004a1d0b; ModelTransform: 31.8897,63.7794,0,90,0,0,0,0,0
R27 = 1k: Convert to PCB: yes; UniqueId: ggebc1ed0bbe25fab2f; ModelTransform: 31.8897,63.7794,0,90,0,0,0,0,0
R28 = 1k: Convert to PCB: yes; UniqueId: ggee94924af568416b5; ModelTransform: 31.8897,63.7794,0,90,0,0,0,0,0
R29 = 4D02WGF1002TCE: Manufacturer: UNI-ROYAL(厚声); Convert to PCB: yes; UniqueId: gge07544b47d1892801; OriginModelName: R0402-8P_L2.0-W1.0-H0.5; ModelTransform: 78.74,39.37,0,180,0,0,0,0,0
R30 = 4D02WGF1002TCE: Manufacturer: UNI-ROYAL(厚声); Convert to PCB: yes; UniqueId: gge77dae21efa63f364; OriginModelName: R0402-8P_L2.0-W1.0-H0.5; ModelTransform: 78.74,39.37,0,180,0,0,0,0,0
R31 = 1k: Convert to PCB: yes; UniqueId: ggec1dfd3b01c2c65db; ModelTransform: 31.8897,63.7794,0,90,0,0,0,0,0
R32 = RC0402FR-0710KL: Manufacturer: YAGEO(国巨); Convert to PCB: yes; UniqueId: ggefd6f330f786ae1bc; OriginModelName: R0402_L1.0-W0.5-H0.4; ModelTransform: 39.37,19.685,0,0,0,0,0,0.001,0
R33 = RC0402FR-0710KL: Manufacturer: YAGEO(国巨); Convert to PCB: yes; UniqueId: ggeb12758e104cafe18; OriginModelName: R0402_L1.0-W0.5-H0.4; ModelTransform: 39.37,19.685,0,0,0,0,0,0.001,0
R34 = RC0402FR-0710KL: Manufacturer: YAGEO(国巨); Convert to PCB: yes; UniqueId: gge03b7dc052d3712c7; OriginModelName: R0402_L1.0-W0.5-H0.4; ModelTransform: 39.37,19.685,0,0,0,0,0,0.001,0
R35 = RC0402FR-0710KL: Manufacturer: YAGEO(国巨); Convert to PCB: yes; UniqueId: gge0e8147650a4c1f88; OriginModelName: R0402_L1.0-W0.5-H0.4; ModelTransform: 39.37,19.685,0,0,0,0,0,0.001,0
R36 = RC0402FR-0710KL: Manufacturer: YAGEO(国巨); Convert to PCB: yes; UniqueId: gge4607301ef64e3a36; OriginModelName: R0402_L1.0-W0.5-H0.4; ModelTransform: 39.37,19.685,0,0,0,0,0,0.001,0
SDO1 = BMI270: Convert to PCB: yes; UniqueId: ggebe24d6cd85f7bebd; OriginModelName: LGA-14_L2.5-W3.0-H0.9-P0.50; ModelTransform: 118.11,98.425,0,0,0,0,0,0.001,0
SW1 = TS-1073B-A2B2-D4: Manufacturer: Yuandi(元迪); Convert to PCB: yes; UniqueId: gge673417370de76ff0; ModelTransform: 188.976,137.795,0,0,0,0,0.66,24.554,-15.748
U1 = SPX3819M5-L-3-3/TR: Manufacturer: MaxLinear(迈凌); Convert to PCB: yes; UniqueId: ggead5155cd06fa3072; OriginModelName: SOT-23-5_L2.9-W1.6-H1.1-LS2.8-P0.95; ModelTransform: 114.173,109.636,0,180,0,0,0,-0.001,0
U2 = MP9943: Convert to PCB: yes; UniqueId: ggeb87cc7bca5c8949e
U3 = MP9943: Convert to PCB: yes; UniqueId: gge5de058e1dcebc45f
U4 = MPU-6500: Manufacturer: TDK InvenSense(应美盛); Convert to PCB: yes; UniqueId: gge6fb0faa0bb8ee760; OriginModelName: QFN-24_L3.0-W3.0-H0.9-P0.40-BL-EP; ModelTransform: 118.11,118.11,0,90,0,0,0,0,0
U5 = 8M/3213: Convert to PCB: yes; UniqueId: ggee29a88e2d2ac9ac9; ModelTransform: 125.984,51.181,0,0,0,0,-0.592,-0.591,0
U6 = AT32F435VMT7: Manufacturer: ARTERY（雅特力）; Convert to PCB: yes; UniqueId: ggece277d5420079038; OriginModelName: LQFP-100_L14.0-W14.0-H1.4-LS16.0-P0.50; ModelTransform: 629.921,629.921,0,270,0,0,0,0,0
U7 = BMP280: Manufacturer: Bosch; Convert to PCB: yes; UniqueId: gge447de30e0e3d1cf2; OriginModelName: LGA-8_L2.0-W2.5-H1.0-P0.65; ModelTransform: 98.425,78.74,0,270,0,0,0.005,-0.001,0
U8 = 2016晶振/27M: Convert to PCB: yes; UniqueId: gge8a1c1357ed2894bc; OriginModelName: OSC-SMD_4P-L2.0-W1.6-H0.8; ModelTransform: 78.74,62.992,0,0,0,0,0,0,0
U9 = AT7456E: Manufacturer: ZHONGKEWEI; Convert to PCB: yes; UniqueId: gge0ef7d474198b7014; ModelTransform: 381.889,251.968,0,0,0,0,0,0.005,0
U10 = W25N01GVZEIG: Manufacturer: Winbond Elec; Convert to PCB: yes; UniqueId: ggee63176ef5aab684c; OriginModelName: WSON-8_L8.0-W6.0-H0.8-P1.27; ModelTransform: 315.7474,236.22,0,0,0,0,0,0,0
U11 = ZX-SH1.0-10PWT: Manufacturer: Megastar(兆星); Convert to PCB: yes; UniqueId: gge7200404e0632cc6f; ModelTransform: 486.613,198.8185,0,0,0,0,-0.001,-6.062,0
U12 = SPX3819M5-L-3-3/TR: Manufacturer: MaxLinear(迈凌); Convert to PCB: yes; UniqueId: gge70c12bce5ebcd7d5; OriginModelName: SOT-23-5_L2.9-W1.6-H1.1-LS2.8-P0.95; ModelTransform: 114.173,109.636,0,180,0,0,0,-0.001,0
USB1 = TYPEC-304A-ACP16L: Manufacturer: XUNPU(讯普); Convert to PCB: yes; UniqueId: gge27292bd05ad1f100; ModelTransform: 351.9678,298.4246,0,180,0,0,0,-45.275,-39.37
